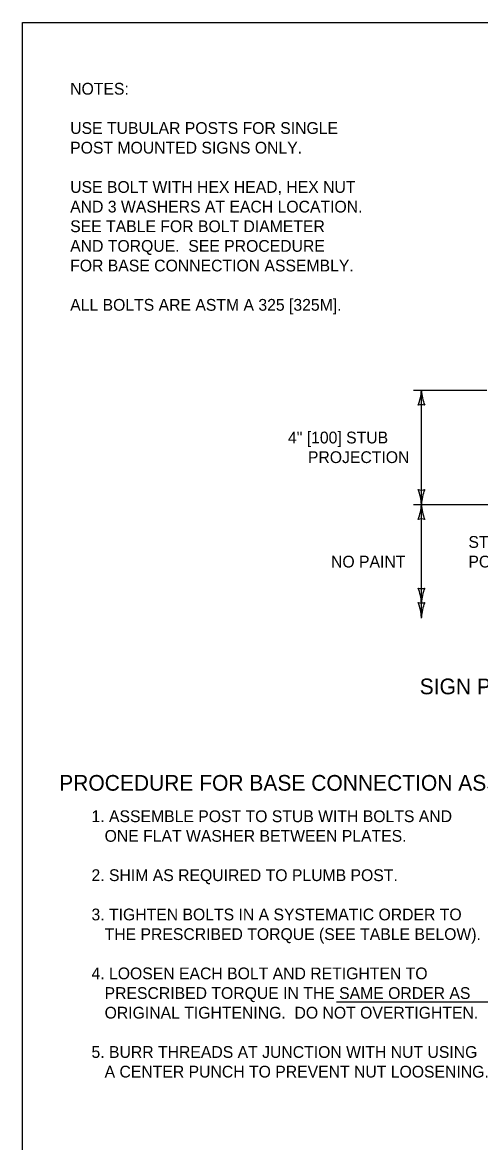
# Model space of a CAD drawing. Extents: x 49991 to 81321, y 49988 to 50028.
# Drawn here: x 49999.38 to 50001.72, y 49993.3 to 49999 of the extents above; entities that cross this region are included whole.
import ezdxf

# ---------------------------------------------------------------- set-up
doc = ezdxf.new("R2010")
doc.units = 0
for name, color, linetype in [('Level 1', 7, 'Continuous'), ('Level 2', 7, 'Continuous'), ('Level 3', 7, 'Continuous')]:
    doc.layers.add(name, color=color, linetype=linetype)

msp = doc.modelspace()

# ---------------------------------------------------------------- linework, layer by layer
at = {"layer": 'Level 1'}
msp.add_lwpolyline([(49999.3835, 49998.9992), (50016.7501, 49998.9992), (50016.7501, 49987.7988), (49999.3835, 49987.7988)], close=True, dxfattribs=at)
at = {"layer": 'Level 2'}
msp.add_line((50000.9845, 49994.0131), (50002.0451, 49994.0131), dxfattribs=at)
at = {"layer": 'Level 3'}
for p, q in [((50001.3761, 49997.1267), (50001.749, 49997.1267)), ((50001.4161, 49996.5455), (50001.4161, 49997.1267)), ((50001.3761, 49996.5455), (50003.0293, 49996.5455)), ((50001.4161, 49995.967), (50001.4161, 49996.5455))]:
    msp.add_line(p, q, dxfattribs=at)
for centre, radius, start, end in [((50001.194, 49997.1358), 0.2223, 337.456, 357.6395), ((50001.6488, 49997.1381), 0.233, 182.8273, 202.0772), ((50001.4161, 49996.9984), 0.0548, 72.1388, 107.8612), ((50001.4161, 49996.6737), 0.0548, 252.1388, 287.8612), ((50001.1834, 49996.534), 0.233, 2.8273, 22.0772), ((50001.6383, 49996.5363), 0.2223, 157.456, 177.6395), ((50001.194, 49996.5546), 0.2223, 337.456, 357.6395), ((50001.6488, 49996.5569), 0.233, 182.8273, 202.0772), ((50001.4161, 49996.4172), 0.0548, 72.1388, 107.8612), ((50001.4161, 49996.1721), 0.0548, 252.1388, 287.8612), ((50001.1834, 49996.0324), 0.233, 2.8273, 22.0772), ((50001.6383, 49996.0347), 0.2223, 157.456, 177.6395), ((50001.4161, 49996.0987), 0.0548, 252.1388, 287.8612), ((50001.1834, 49995.959), 0.233, 2.8273, 22.0772), ((50001.6383, 49995.9613), 0.2223, 157.456, 177.6395)]:
    msp.add_arc(centre, radius, start, end, dxfattribs=at)

# ---------------------------------------------------------------- texts
at = {"layer": 'Level 2'}
for s, height, p in [('NOTES:', 0.06, (49999.627, 49998.6315)), ('USE TUBULAR POSTS FOR SINGLE', 0.06, (49999.627, 49998.4315)), ('POST MOUNTED SIGNS ONLY.', 0.06, (49999.627, 49998.3315)), ('USE BOLT WITH HEX HEAD, HEX NUT', 0.06, (49999.627, 49998.1315)), ('AND 3 WASHERS AT EACH LOCATION.', 0.06, (49999.627, 49998.0315)), ('SEE TABLE FOR BOLT DIAMETER', 0.06, (49999.627, 49997.9315)), ('AND TORQUE.  SEE PROCEDURE', 0.06, (49999.627, 49997.8315)), ('FOR BASE CONNECTION ASSEMBLY.', 0.06, (49999.627, 49997.7315)), ('ALL BOLTS ARE ASTM A 325 [325M].', 0.06, (49999.627, 49997.5315)), ('4" [100] STUB', 0.06, (50000.7366, 49996.8561)), ('PROJECTION', 0.06, (50000.8381, 49996.7561)), ('STUB', 0.06, (50001.6557, 49996.3245)), ('NO PAINT', 0.06, (50000.9558, 49996.2245)), ('POST', 0.06, (50001.6557, 49996.2245)), ('SIGN POST AND STUB POST DETAILS', 0.08, (50001.4076, 49995.5791)), ('PROCEDURE FOR BASE CONNECTION ASSEMBLY', 0.08, (49999.5711, 49995.0883)), ('1. ASSEMBLE POST TO STUB WITH BOLTS AND', 0.06, (49999.7355, 49994.9283)), ('   ONE FLAT WASHER BETWEEN PLATES.', 0.06, (49999.7355, 49994.8283)), ('2. SHIM AS REQUIRED TO PLUMB POST.', 0.06, (49999.7355, 49994.6283)), ('3. TIGHTEN BOLTS IN A SYSTEMATIC ORDER TO', 0.06, (49999.7355, 49994.4283)), ('   THE PRESCRIBED TORQUE (SEE TABLE BELOW).', 0.06, (49999.7355, 49994.3283)), ('4. LOOSEN EACH BOLT AND RETIGHTEN TO', 0.06, (49999.7355, 49994.1283)), ('   PRESCRIBED TORQUE IN THE SAME ORDER AS', 0.06, (49999.7355, 49994.0283)), ('   ORIGINAL TIGHTENING.  DO NOT OVERTIGHTEN.', 0.06, (49999.7355, 49993.9283)), ('5. BURR THREADS AT JUNCTION WITH NUT USING', 0.06, (49999.7355, 49993.7283)), ('   A CENTER PUNCH TO PREVENT NUT LOOSENING.   ', 0.06, (49999.7355, 49993.6283))]:
    msp.add_text(s, height=height, dxfattribs=at).set_placement(p)

doc.saveas('drawing.dxf')
